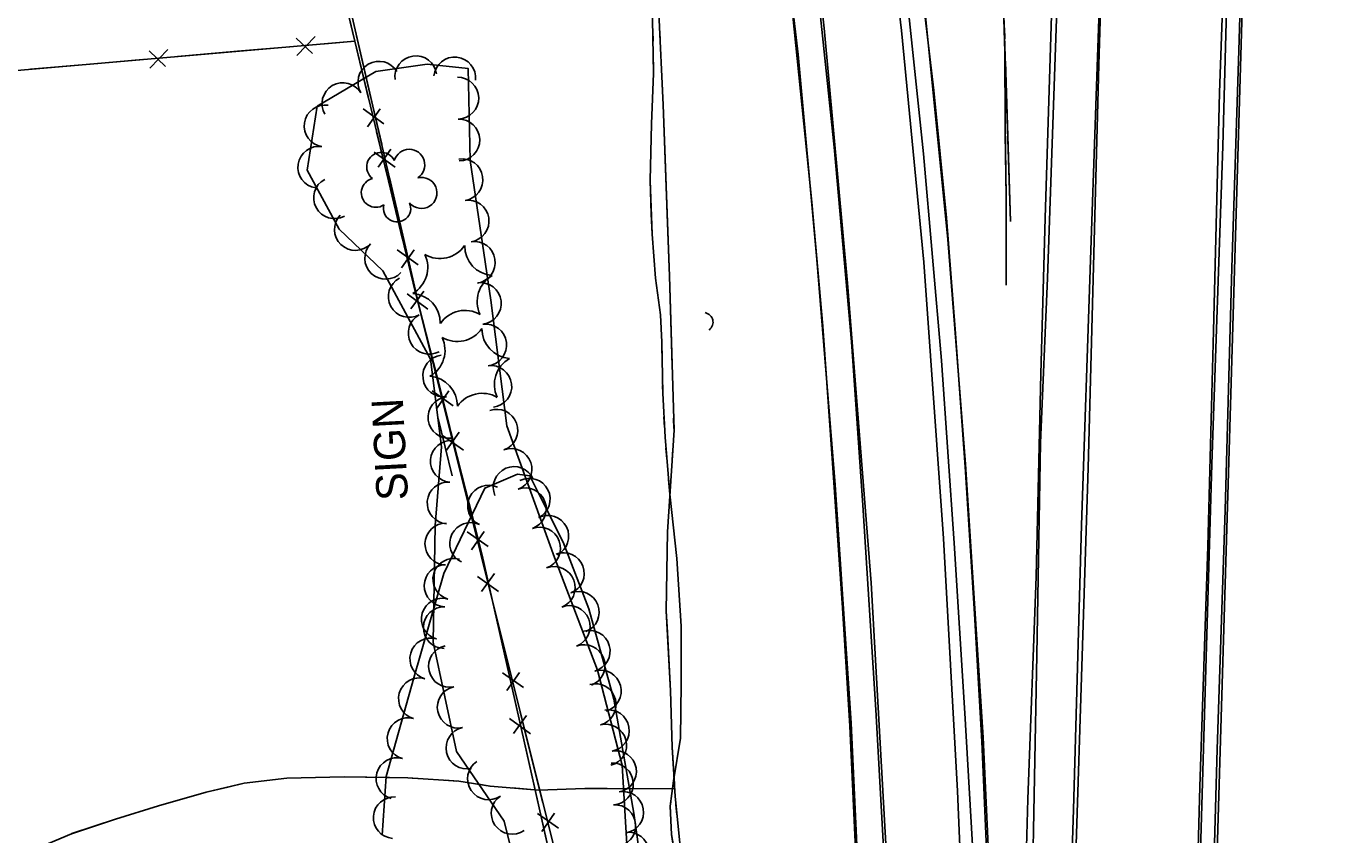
# Model space of a CAD drawing. Extents: x 353423 to 364002, y 127000 to 201942.
# Drawn here: x 361220 to 361468.8, y 132273.2 to 132428 of the extents above; entities that cross this region are included whole.
import ezdxf

# ---------------------------------------------------------------- set-up
doc = ezdxf.new("R2010")
doc.units = 0
for name, color, linetype in [('E_DTM_SlopeBottom', 7, 'Continuous'), ('E_DTM_SlopeTop', 7, 'Continuous'), ('E_FEN_Generic', 7, 'Continuous'), ('E_LAND_BrushLine', 7, 'Continuous'), ('E_STRUCT_WingWall', 7, 'Continuous')]:
    doc.layers.add(name, color=color, linetype=linetype)

msp = doc.modelspace()

# ---------------------------------------------------------------- linework, layer by layer
at = {"layer": 'E_DTM_SlopeBottom'}
for p, q in [((361271.7, 132425.62), (361274.8, 132422.66)), ((361271.81, 132422.33), (361275.28, 132425.93)), ((361243.57, 132423.17), (361246.67, 132420.22)), ((361243.68, 132419.89), (361247.15, 132423.48)), ((361288.47, 132409.24), (361284.47, 132412.09)), ((361285.29, 132408.65), (361287.71, 132412.1)), ((361286.6, 132403.82), (361290.59, 132400.93)), ((361289.79, 132404.39), (361287.34, 132400.95)), ((361294.99, 132382.24), (361290.98, 132385.09)), ((361291.81, 132381.65), (361294.23, 132385.1)), ((361292.88, 132376.68), (361296.87, 132373.79)), ((361296.07, 132377.24), (361293.61, 132373.81)), ((361301.69, 132355.3), (361297.66, 132358.11)), ((361298.51, 132354.68), (361300.9, 132358.15)), ((361302.83, 132350.25), (361300.44, 132346.76)), ((361299.65, 132349.62), (361303.7, 132346.81)), ((361308.41, 132328.35), (361304.38, 132331.16)), ((361305.23, 132327.73), (361307.63, 132331.2)), ((361309.57, 132323.18), (361307.09, 132319.75)), ((361306.37, 132322.63), (361310.35, 132319.72)), ((361315.13, 132301.4), (361311.1, 132304.21)), ((361311.96, 132300.78), (361314.35, 132304.25)), ((361312.5, 132295.45), (361316.48, 132292.54)), ((361315.7, 132296), (361313.22, 132292.57)), ((361321.86, 132274.45), (361317.83, 132277.27)), ((361318.68, 132273.83), (361321.08, 132277.3))]:
    msp.add_line(p, q, dxfattribs=at)
for points in [[(361233.39, 132631.68), (361261.76, 132514.55), (361280.98, 132435.84), (361295.28, 132374.03), (361307.24, 132326.67), (361320.94, 132265.93), (361331.86, 132221.31), (361327.11, 132161.24), (361322.61, 132097.07), (361319.05, 132047.36), (361315.93, 132009.93)], [(361209.41, 132418.68), (361282.87, 132425.06), (361261.85, 132512.98)], [(361277.13, 132424.56), (361282.87, 132425.06), (361281.55, 132430.61)], [(361326.98, 132153.07), (361330.85, 132200.3), (361329.76, 132229.82), (361322.65, 132265.04), (361321.26, 132269.67), (361294.05, 132378.74), (361282.87, 132425.06)], [(361285.52, 132414.09), (361282.87, 132425.06)], [(361283.24, 132426.08), (361285.79, 132415.05)], [(361249.01, 132422.12), (361260.43, 132423.11)], [(361260.43, 132423.11), (361270.48, 132423.99)], [(361220.88, 132419.67), (361232.31, 132420.67)], [(361232.31, 132420.67), (361242.36, 132421.54)], [(361285.79, 132415.05), (361288.03, 132405.35)], [(361289.39, 132398.06), (361287.06, 132407.71)], [(361292.04, 132387.09), (361289.39, 132398.06)], [(361289.52, 132398.93), (361292.07, 132387.9)], [(361292.07, 132387.9), (361294.31, 132378.2)], [(361295.96, 132371.08), (361294.05, 132378.74), (361293.58, 132380.71)], [(361295.84, 132371.8), (361298.61, 132360.82)], [(361298.7, 132360.12), (361295.96, 132371.08)], [(361298.61, 132360.82), (361301.05, 132351.17)], [(361302.69, 132344.13), (361300.28, 132353.76)], [(361302.66, 132344.79), (361305.44, 132333.81)], [(361305.42, 132333.17), (361302.69, 132344.13)], [(361305.44, 132333.81), (361307.24, 132326.67), (361307.81, 132324.14)], [(361309.41, 132317.18), (361307.01, 132326.81)], [(361309.26, 132317.72), (361311.75, 132306.68)], [(361312.14, 132306.23), (361309.41, 132317.18)], [(361311.75, 132306.68), (361313.94, 132296.97)], [(361316.13, 132290.23), (361313.73, 132299.86)], [(361315.39, 132290.55), (361317.88, 132279.5)], [(361318.87, 132279.28), (361316.13, 132290.23)], [(361317.88, 132279.5), (361320.07, 132269.79)]]:
    msp.add_lwpolyline(points, dxfattribs=at)
msp.add_ellipse((361348.65, 132371.06), major_axis=(2.69, 0.64), ratio=0.781159, start_param=5.356084, end_param=7.210314, dxfattribs=at)
at = {"layer": 'E_DTM_SlopeTop'}
for points in [[(361464.86, 132976.42), (361463.91, 132906.98), (361461.73, 132832.23), (361459.86, 132768.05), (361457.85, 132696.75), (361455.67, 132625.71), (361453.62, 132560.67), (361451.05, 132485.72), (361448.89, 132404.98), (361446.76, 132344.1), (361444.57, 132270.14), (361442.39, 132202.43), (361439.91, 132127.01), (361438.1, 132067.85), (361435.92, 131995.48), (361433.75, 131930.16), (361431.26, 131854.06), (361428.74, 131770.89), (361425.76, 131686.63)], [(361430.16, 131701.25), (361432.11, 131769.04), (361434.08, 131831.72), (361436.21, 131903.29), (361438.21, 131965.27), (361441.2, 132038.01), (361443.74, 132123.15), (361446.01, 132200.48), (361447.68, 132265.76), (361449.97, 132342.45), (361452.49, 132428.72), (361454.55, 132486.96), (361457.23, 132581.29), (361459.23, 132650.77), (361462.07, 132729.55), (361463.85, 132802.85), (361466.65, 132872.95), (361467.83, 132941.11), (361468.79, 132976.08)], [(361382.82, 131645.67), (361383.66, 131706.48), (361384.51, 131786.08), (361385.45, 131845.88), (361386.02, 131923.66), (361386.78, 132008.6), (361387.69, 132086.22), (361388.02, 132124.3), (361387.98, 132159.95), (361386.49, 132215.67), (361384.63, 132267.99), (361381.61, 132321.39), (361377.11, 132378.72), (361372.64, 132427.53), (361367.15, 132475.91), (361360.11, 132527.54), (361351.65, 132583.36), (361339.44, 132654.21), (361329.03, 132707.61), (361316.5, 132764.48), (361306.42, 132807.97), (361292.18, 132864.05), (361268.84, 132946.34)], [(361414.27, 132054.07), (361417.03, 132148.36), (361419.64, 132233.34), (361423.12, 132343.39), (361425.19, 132420.55), (361427.64, 132502.65), (361430.77, 132609.88), (361433.92, 132713.46), (361437.4, 132827.09)], [(361306.62, 132783.09), (361317.32, 132735.17), (361326.14, 132692.89), (361333.83, 132653.34), (361341.74, 132609.5), (361348.12, 132572.55), (361353, 132538.45), (361358.49, 132499.45), (361363.08, 132461.46), (361367.66, 132422.52), (361371.26, 132383.27), (361374.72, 132340.17), (361377.77, 132294.56), (361379.9, 132249.28), (361381.43, 132202.89), (361381.91, 132174.81), (361382.14, 132130.34), (361381.89, 132072.84), (361381.6, 132012.57), (361381.1, 131957.1), (361380.16, 131891.06), (361379.21, 131819), (361378.3, 131741.31), (361377.36, 131657.69)], [(361332.89, 132760.01), (361342.05, 132718.1), (361350.98, 132672.92), (361360.17, 132622.85), (361367.37, 132579.35), (361374.66, 132529.78), (361381.47, 132476.56), (361387.42, 132427.12), (361391.7, 132382.77), (361395.47, 132329.89), (361398.12, 132281.51), (361400.1, 132234.7), (361401.88, 132168.85), (361401.98, 132110.49)], [(361402.89, 132234.99), (361401.24, 132266.8), (361399.53, 132296.47), (361397.49, 132329), (361395.06, 132363.96), (361391.64, 132403.47), (361388.09, 132437.5), (361383.83, 132474.15), (361379.08, 132509.85), (361374.34, 132543.08), (361369.18, 132578.88), (361363.07, 132616.62), (361359.25, 132638.42)], [(361410.14, 132235.47), (361405.13, 132235.66), (361404.59, 132245.71), (361403.7, 132270.43), (361402.8, 132291.01), (361401.36, 132315.5), (361399.6, 132343.63), (361397.69, 132369.96), (361396.02, 132391.27), (361393.63, 132415.6), (361390.89, 132438.78), (361388.22, 132462.64), (361384.61, 132491.79), (361380.27, 132523.05), (361375.72, 132555.31), (361371.37, 132583.52), (361366.84, 132612.53), (361362.36, 132637.69)], [(361402.47, 131708.5), (361403.61, 131748.04), (361405.15, 131797.25), (361406.55, 131840.33), (361407.95, 131886.05), (361409.49, 131933.8), (361410.97, 131982.15), (361412.67, 132031.07), (361414.24, 132081), (361415.79, 132133.35), (361417.08, 132176.81), (361418.6, 132224.98), (361420.29, 132278), (361421.87, 132332.44), (361423.58, 132383.2), (361425.48, 132438.64), (361427.02, 132487.77), (361428.48, 132532.73), (361429.65, 132577.86), (361430.83, 132613.31), (361431.54, 132638.48)], [(361387.38, 132136.5), (361387.18, 132165.21), (361386.89, 132189.17), (361386.25, 132218.35), (361385.35, 132242.95), (361384.2, 132267.3), (361382.53, 132297.1), (361380.06, 132336.24), (361377.89, 132367.52), (361374.57, 132404.77), (361371.38, 132435.28), (361368.04, 132464.76), (361364.08, 132496.38), (361359.79, 132526.42), (361355.31, 132557.02), (361350.87, 132586.19), (361345.48, 132618.57), (361343.02, 132632.8)], [(361426.78, 131719.89), (361427.54, 131748.12), (361428.88, 131787.86), (361430.24, 131832.07), (361431.74, 131875.77), (361433.35, 131922.98), (361434.73, 131974.84), (361435.99, 132016.13), (361437.67, 132064.09), (361439.33, 132111.67), (361440.8, 132161.15), (361441.72, 132192.29), (361443.23, 132237.42), (361444.48, 132282.34), (361446.01, 132328.42), (361447.07, 132369.59), (361448.21, 132415.19), (361450.05, 132467.24), (361451.4, 132504.26), (361452.5, 132544.18), (361453.88, 132587.84), (361455.41, 132632.51)], [(361442.54, 132116.47), (361443.61, 132156.59), (361444.92, 132196.75), (361446.51, 132244.46), (361447.8, 132289.55), (361449.29, 132335.3), (361450.58, 132381.65), (361451.9, 132423.27), (361453.12, 132464.39), (361453.77, 132486.18), (361454.92, 132520.96), (361456.39, 132573.1), (361457.79, 132616.02), (361458.38, 132631.83)], [(361382.1, 132132.35), (361382.25, 132154.32), (361382.19, 132169.32), (361381.78, 132189.18), (361381.37, 132207.87), (361380.71, 132224.77), (361379.79, 132245.94), (361378.76, 132267.66), (361377.54, 132293.98), (361376.12, 132316.63), (361374.22, 132344.3), (361372.41, 132370.52), (361370.27, 132394.23), (361367.82, 132418.62), (361365.09, 132444.9), (361361.51, 132474.8), (361357.76, 132504.91), (361354.56, 132527.82), (361350.58, 132554.35), (361346.7, 132579.74), (361342.01, 132607.75), (361338.03, 132631.1)], [(361410.14, 132235.47), (361410.61, 132245.57), (361411.59, 132280.01), (361413.18, 132322.63), (361414.09, 132361.42), (361414.88, 132391.15), (361416.12, 132430.01), (361417.35, 132467.29), (361418.41, 132488.65), (361419.47, 132523.09), (361420.39, 132556.79), (361421.45, 132591.27), (361422.79, 132627.83)], [(361417.74, 132449.6), (361415.35, 132379.73), (361414, 132348.19), (361413.31, 132307.61), (361412.4, 132260.7), (361411.42, 132239.21), (361410.76, 132236.57), (361409.45, 132236.34), (361407.62, 132236.45), (361405.59, 132236.52), (361403.02, 132291.8), (361399.64, 132344.11), (361396.26, 132387.08), (361390.76, 132442.63)]]:
    msp.add_lwpolyline(points, dxfattribs=at)
at = {"layer": 'E_FEN_Generic'}
for points in [[(361335.41, 132262.73), (361334.03, 132286.5), (361329.3, 132304.7), (361321.08, 132326.25), (361311.97, 132351.42), (361308.92, 132375.5), (361304.95, 132402.19), (361304.55, 132419.84), (361296.72, 132420.65), (361286.9, 132419.27), (361275.67, 132412.59), (361273.81, 132400.36), (361279.91, 132389.06), (361288.28, 132381.13), (361297.39, 132364.23), (361299.48, 132347.45), (361298.28, 132332.36), (361297.87, 132310.06), (361302.35, 132289.12), (361311.48, 132275.81), (361316.4, 132255.86)], [(361339.4, 132254.55), (361336.26, 132277.34), (361332.45, 132299.17), (361327.62, 132316.43), (361322.73, 132329.17), (361318.49, 132337.64), (361316.33, 132341.89), (361313.97, 132342.2), (361307.78, 132339.53), (361299.94, 132323.17), (361294.19, 132303.25), (361288.87, 132284.33), (361288.09, 132273.1)]]:
    msp.add_lwpolyline(points, dxfattribs=at)
for centre, radius, start, end in [((361287.5, 132417.19), 4, 30.779, 210.7637), ((361294.56, 132418.24), 4, 8.0082, 187.9929), ((361302, 132418), 4, 354.049, 174.0337), ((361302.59, 132414.14), 4, 271.2921, 91.2768), ((361280.62, 132413.1), 4, 30.779, 210.7637), ((361277.22, 132408.83), 4, 81.3268, 261.3114), ((361302.77, 132406.14), 4, 271.2921, 91.2768), ((361276.01, 132400.92), 4, 81.3268, 261.3114), ((361287.94, 132400.99), 2.78, 25.9259, 233.6989), ((361293.3, 132401.39), 2.97, 302.955, 164.1889), ((361303.38, 132398.54), 4, 278.4699, 98.4546), ((361279.03, 132395.09), 4, 118.3764, 298.3611), ((361286.91, 132396.04), 2.78, 102.6029, 303.614), ((361295.63, 132396.02), 2.97, 220.6058, 103.5791), ((361290.97, 132393.06), 2.61, 165.311, 23.2437), ((361304.55, 132390.63), 4, 278.4699, 98.4546), ((361283, 132389.02), 4, 136.5365, 316.5211), ((361288.8, 132383.51), 4, 136.5365, 316.5211), ((361299.18, 132389.17), 5.72, 239.7427, 325.5076), ((361309.62, 132385.9), 5.72, 179.7427, 265.5076), ((361305.73, 132382.72), 4, 278.4699, 98.4546), ((361291.12, 132381.76), 5.72, 299.7427, 25.5076), ((361312.01, 132375.22), 5.72, 119.7427, 205.5076), ((361293.32, 132376.19), 4, 118.331, 298.3157), ((361306.89, 132374.85), 4, 277.2189, 97.2036), ((361293.52, 132371.08), 5.72, 359.7427, 85.5076), ((361297.11, 132369.15), 4, 118.331, 298.3157), ((361303.96, 132367.81), 5.72, 59.7427, 145.5076), ((361307.9, 132366.91), 4, 277.2189, 97.2036), ((361294.42, 132365.89), 5.72, 299.7427, 25.5076), ((361302.47, 132373.3), 5.72, 239.7427, 325.5076), ((361312.91, 132370.03), 5.72, 179.7427, 265.5076), ((361299.9, 132360.98), 4, 97.1186, 277.1032), ((361308.9, 132358.98), 4, 277.2189, 97.2036), ((361315.3, 132359.36), 5.72, 119.7427, 205.5076), ((361296.81, 132355.22), 5.72, 359.7427, 85.5076), ((361307.25, 132351.95), 5.72, 59.7427, 145.5076), ((361300.89, 132353.04), 4, 97.1186, 277.1032), ((361310.04, 132350.6), 4, 289.9101, 109.8947), ((361301.36, 132344.66), 4, 85.4612, 265.4459), ((361312.76, 132343.08), 4, 289.9101, 109.8947), ((361313.34, 132339.67), 3.97, 23.3659, 203.3506), ((361300.73, 132336.69), 4, 85.4612, 265.4459), ((361316.27, 132337.42), 3.97, 296.8952, 116.8799), ((361308.45, 132336.12), 3.97, 64.4031, 244.3878), ((361315.49, 132335.56), 4, 289.9101, 109.8947), ((361300.31, 132328.83), 4, 88.9516, 268.9362), ((361305.02, 132328.97), 3.97, 64.4031, 244.3878), ((361319.82, 132330.33), 3.97, 296.5781, 116.5628), ((361318.21, 132328.03), 4, 289.9101, 109.8947), ((361301.8, 132322.1), 3.97, 73.904, 253.8887), ((361322.79, 132323.2), 3.97, 291.0156, 111.0003), ((361300.16, 132320.84), 4, 88.9516, 268.9362), ((361321.03, 132320.51), 4, 290.8798, 110.8645), ((361299.59, 132314.48), 3.97, 73.904, 253.8887), ((361325.64, 132315.79), 3.97, 291.0156, 111.0003), ((361300.02, 132312.84), 4, 88.9516, 268.9362), ((361323.88, 132313.04), 4, 290.8798, 110.8645), ((361297.39, 132306.86), 3.97, 73.904, 253.8887), ((361327.73, 132308.34), 3.97, 285.6599, 105.6446), ((361301, 132305.43), 4, 102.073, 282.0577), ((361326.73, 132305.56), 4, 290.8798, 110.8645), ((361295.22, 132299.24), 3.97, 74.2973, 254.2819), ((361329.87, 132300.7), 3.97, 285.6599, 105.6446), ((361302.67, 132297.61), 4, 102.073, 282.0577), ((361328.85, 132298.1), 4, 284.568, 104.5527), ((361293.07, 132291.6), 3.97, 74.2973, 254.2819), ((361331.4, 132293.13), 3.97, 279.91, 99.8947), ((361304.34, 132289.79), 4, 102.073, 282.0577), ((361330.86, 132290.36), 4, 284.568, 104.5527), ((361332.76, 132285.31), 3.97, 279.91, 99.8947), ((361290.92, 132283.96), 3.97, 74.2973, 254.2819), ((361308.46, 132283.9), 4, 124.466, 304.4507), ((361332.14, 132282.91), 4, 273.3385, 93.3232), ((361312.99, 132277.31), 4, 124.466, 304.4507), ((361334.13, 132277.5), 3.97, 279.91, 99.8947), ((361290.4, 132276.47), 3.97, 86.0327, 266.0174), ((361332.6, 132274.93), 4, 273.3385, 93.3232), ((361335.22, 132269.71), 3.97, 277.8462, 97.8309)]:
    msp.add_arc(centre, radius, start, end, dxfattribs=at)
at = {"layer": 'E_LAND_BrushLine'}
msp.add_line((361301.53, 132341.88), (361298.86, 132352.86), dxfattribs=at)
at = {"layer": 'E_STRUCT_WingWall'}
for points in [[(361408.28, 132390.53), (361406.57, 132443.89), (361406.18, 132488.15), (361405.54, 132562.46), (361403.77, 132630.41), (361404.98, 132674.65), (361404.99, 132685.99), (361405.14, 132710.45), (361407.43, 132788.45), (361408.92, 132857.57), (361408.97, 132919.75), (361408.66, 132983.74)], [(361407.47, 132378.39), (361407.43, 132395.32), (361407.26, 132409.24), (361407.17, 132423.03), (361406.66, 132439.84), (361406.64, 132453.05), (361406.69, 132470.3), (361406.7, 132482.04), (361406.9, 132488.55)], [(361340.22, 132448.11), (361341.84, 132412.84), (361343.09, 132380.07), (361343.93, 132350.63), (361342.69, 132331.17), (361342.43, 132316.07), (361343.24, 132300.76), (361343.59, 132289.94), (361344.14, 132280.54), (361345.33, 132268.49)], [(361339.76, 132432.72), (361340.02, 132418.84), (361339.61, 132409.2), (361339.37, 132398.38), (361339.73, 132388.09), (361340.36, 132379.72), (361341.33, 132372.71), (361341.63, 132367.43), (361341.76, 132357.7), (361342.22, 132349.28), (361343.11, 132338.39), (361344.45, 132326.03), (361345.28, 132313.09), (361345.29, 132302.1), (361345.19, 132291.7), (361343.82, 132283.51), (361343.21, 132278.64), (361343.47, 132273.24), (361344.56, 132266.31)], [(361407.16, 132425.48), (361407.09, 132427.6)], [(361339.87, 132427.02), (361339.91, 132425.02)], [(361341.19, 132426.96), (361341.28, 132424.96)], [(361407.16, 132423.39), (361407.1, 132425.39)], [(361339.98, 132421.02), (361340.02, 132418.84), (361339.61, 132409.2), (361339.37, 132398.38), (361339.59, 132392.04)], [(361341.46, 132420.96), (361341.84, 132412.84), (361342.63, 132391.96)], [(361408.28, 132390.53), (361407.29, 132421.24)], [(361407.21, 132417.39), (361407.19, 132419.39)], [(361407.24, 132411.39), (361407.23, 132413.39)], [(361407.47, 132378.39), (361407.43, 132395.32), (361407.28, 132407.39)], [(361339.59, 132392.04), (361339.73, 132388.09), (361340.36, 132379.72), (361341.33, 132372.71), (361341.63, 132367.43), (361341.68, 132363.14)], [(361342.63, 132391.96), (361343.09, 132380.07), (361343.58, 132362.94)], [(361341.74, 132359.14), (361341.76, 132357.7), (361341.79, 132357.14)], [(361343.69, 132358.94), (361343.75, 132356.93)], [(361342.01, 132353.14), (361342.11, 132351.15)], [(361343.86, 132352.93), (361343.92, 132350.93)], [(361342.39, 132347.16), (361342.55, 132345.16)], [(361343.69, 132346.93), (361343.57, 132344.93)], [(361343.31, 132340.93), (361342.69, 132331.17), (361342.43, 132316.07), (361342.65, 132311.92)], [(361342.88, 132341.18), (361343.11, 132338.39), (361344.45, 132326.03), (361345.28, 132313.09), (361345.28, 132312.29)], [(361342.65, 132311.92), (361343.24, 132300.76), (361343.59, 132289.94), (361344, 132282.96)], [(361345.28, 132312.29), (361345.29, 132302.1), (361345.19, 132291.7), (361343.82, 132283.51), (361343.8, 132283.4)], [(361215.1, 132265.94), (361221.12, 132270.18), (361228.7, 132273.4), (361237.13, 132276.21), (361245.36, 132278.76), (361254.44, 132281.37), (361261.73, 132283.04), (361269.92, 132284.01), (361280.86, 132284.27), (361293.05, 132284.07), (361302.8, 132283.46), (361308.77, 132282.51), (361318, 132281.72), (361326.89, 132282.02), (361330.83, 132282.06), (361331.12, 132282.03), (361344.05, 132282)], [(361258.58, 132282.32), (361261.73, 132283.04), (361269.92, 132284.01), (361280.86, 132284.27), (361289.55, 132284.13)], [(361293.83, 132284.02), (361295.97, 132283.89)], [(361300.23, 132283.62), (361302.37, 132283.48)], [(361228.79, 132273.44), (361237.13, 132276.21), (361245.36, 132278.76), (361254.44, 132281.37), (361258.58, 132282.32)], [(361306.6, 132282.85), (361308.72, 132282.52)], [(361312.99, 132282.15), (361318, 132281.72), (361326.89, 132282.02), (361330.83, 132282.06), (361331.12, 132282.03), (361344.05, 132282)], [(361343.31, 132279.43), (361343.21, 132278.64), (361343.27, 132277.44)], [(361344.3, 132278.97), (361344.49, 132276.98)], [(361343.46, 132273.44), (361343.47, 132273.24), (361343.75, 132271.46)]]:
    msp.add_lwpolyline(points, dxfattribs=at)

# ---------------------------------------------------------------- texts
at = {"layer": 'E_LAND_BrushLine'}
msp.add_text('SIGN', height=6, rotation=93.0278, dxfattribs=at).set_placement((361293.1, 132337.3))

doc.saveas('drawing.dxf')
